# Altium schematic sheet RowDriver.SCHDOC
size A4; DocumentNumber: 5; SheetNumber: 5; SheetTotal: 6
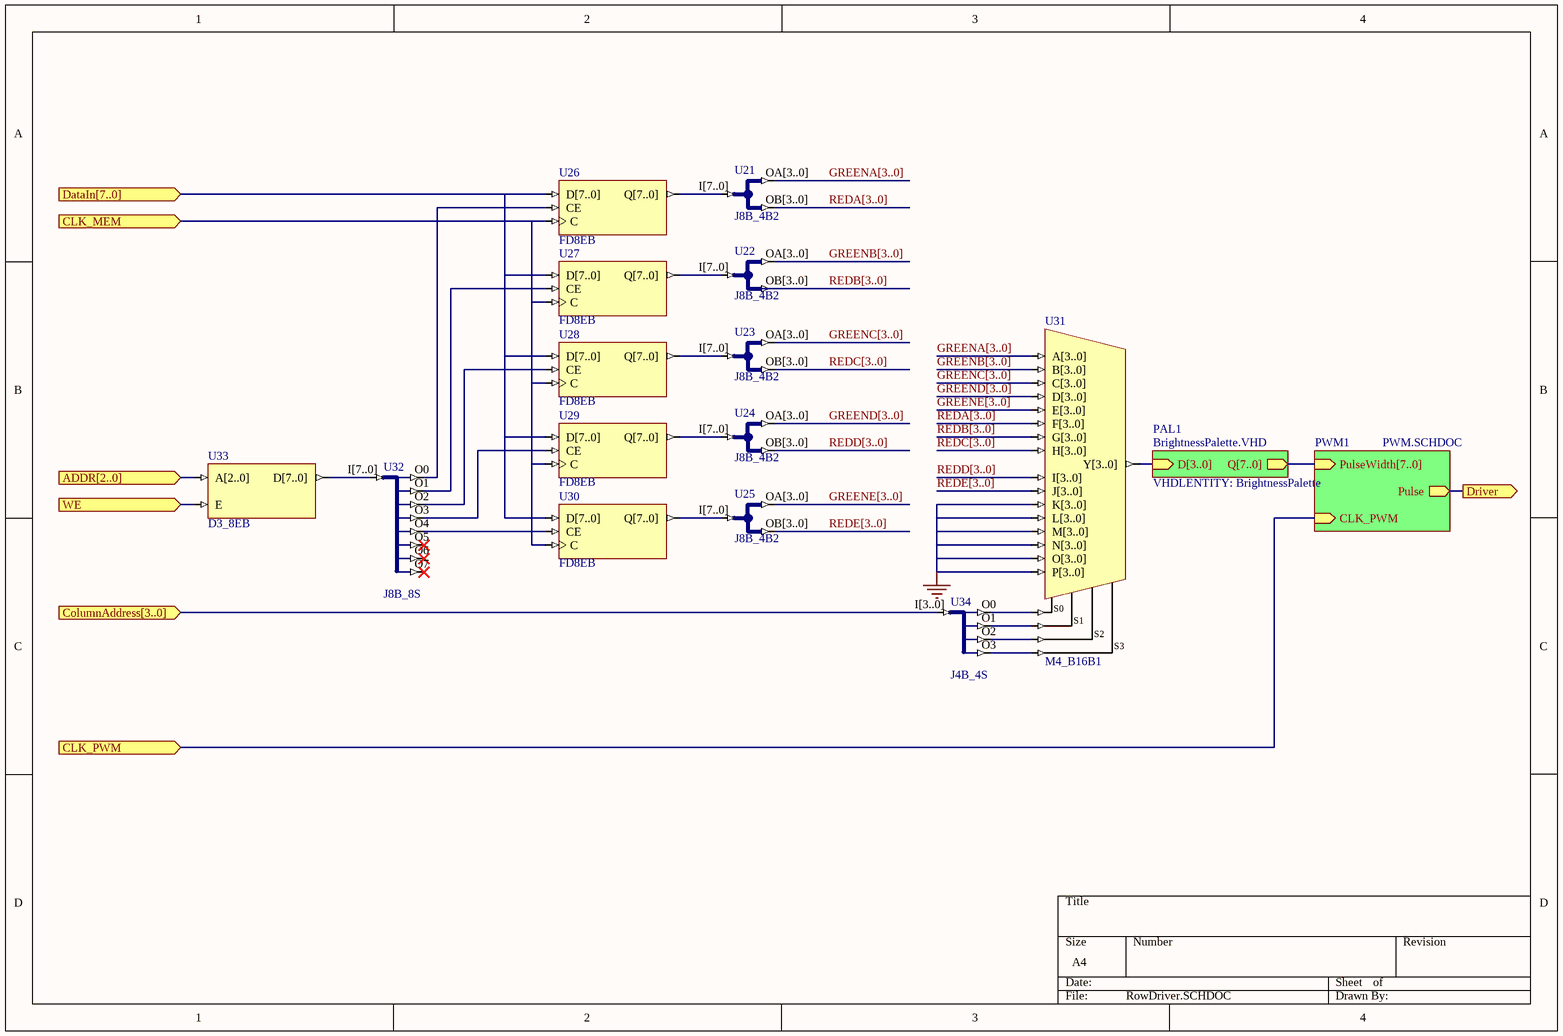
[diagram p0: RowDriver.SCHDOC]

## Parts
U21  J8B_4B2
U22  J8B_4B2
U23  J8B_4B2
U24  J8B_4B2
U25  J8B_4B2
U26  FD8EB
U27  FD8EB
U28  FD8EB
U29  FD8EB
U30  FD8EB
U31  M4_B16B1
U32  J8B_8S
U33  D3_8EB
U34  J4B_4S

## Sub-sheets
PAL1 = BrightnessPalette.VHD: D[3..0] (in), Q[7..0] (out)  | VHDLENTITY: BrightnessPalette
PWM1 = PWM.SCHDOC: Pulse (out), CLK_PWM (in), PulseWidth[7..0] (in)

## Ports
ADDR[2..0] (in), CLK_MEM (in), CLK_PWM (in), ColumnAddress[3..0] (in), DataIn[7..0] (in), Driver (out), WE (in)

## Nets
CLK_MEM: U26.C U27.C U28.C U29.C U30.C ; port CLK_MEM
CLK_PWM: port CLK_PWM, sheet PWM1/CLK_PWM
Driver: port Driver, sheet PWM1/Pulse
WE: U33.E ; port WE
NetU26_CE: U26.CE U32.O0
NetU27_CE: U27.CE U32.O1
NetU28_CE: U28.CE U32.O2
NetU29_CE: U29.CE U32.O3
NetU30_CE: U30.CE U32.O4
NetU31_S0: U31.S0 U34.O0
NetU31_S1: U31.S1 U34.O1
NetU31_S2: U31.S2 U34.O2
NetU31_S3: U31.S3 U34.O3

Not connected (* = marked no-connect by the designer): U21 I[7..0] OA[3..0] OB[3..0]; U22 I[7..0] OA[3..0] OB[3..0]; U23 I[7..0] OA[3..0] OB[3..0]; U24 I[7..0] OA[3..0] OB[3..0]; U25 I[7..0] OA[3..0] OB[3..0]; U26 D[7..0] Q[7..0]; U27 D[7..0] Q[7..0]; U28 D[7..0] Q[7..0]; U29 D[7..0] Q[7..0]; U30 D[7..0] Q[7..0]; U31 A[3..0] B[3..0] C[3..0] D[3..0] E[3..0] F[3..0] G[3..0] H[3..0] I[3..0] J[3..0] K[3..0] L[3..0] M[3..0] N[3..0] O[3..0] P[3..0] Y[3..0]; U32 I[7..0] O5* O6* O7*; U33 A[2..0] D[7..0]; U34 I[3..0]

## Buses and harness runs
bus GREENA[3..0]
bus GREENB[3..0]
bus GREENC[3..0]
bus GREEND[3..0]
bus GREENE[3..0]
bus REDA[3..0]
bus REDB[3..0]
bus REDC[3..0]
bus REDD[3..0]
bus REDE[3..0]
bus sheet PAL1/Q[7..0] = sheet PWM1/PulseWidth[7..0]

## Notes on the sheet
- Labels drawn without touching a wire or pin: GNDBUS[..]

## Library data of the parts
U21-U25 = J8B_4B2: 1 x 8-bit input bus to 2 x 4-Bit output bus; ArchiveName: GENERIC
U26-U30 = FD8EB: 8-Bit D Flip-Flop with Clock Enable, Bus Version; ArchiveName: GENERIC
U31 = M4_B16B1: 16x4-Bit Bus to 1x4-Bit Bus Multiplexer; ArchiveName: GENERIC
U32 = J8B_8S: 8-Bit input bus to 8 single pin outputs; ArchiveName: GENERIC
U33 = D3_8EB: Binary 3- to 8-Bit Decoder with Enable, Bus Version; ArchiveName: GENERIC
U34 = J4B_4S: 4-Bit input bus to 4 Single pin outputs; ArchiveName: GENERIC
